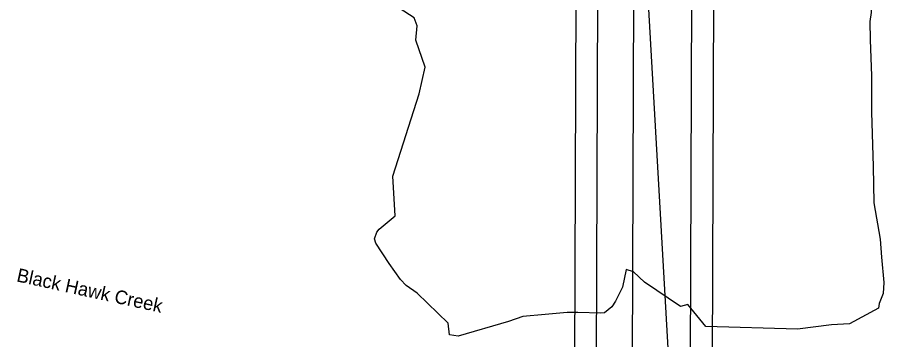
# Model space of a CAD drawing. Extents: x 15359458 to 15360238, y 8797399 to 8799222.
# Drawn here: x 15359587.4 to 15360065.7, y 8798185.5 to 8798363.3 of the extents above; entities that cross this region are included whole.
import ezdxf

# ---------------------------------------------------------------- set-up
doc = ezdxf.new("R2010")
doc.units = 0
for name, color, linetype in [('Alignment', 7, 'Continuous'), ('PhoTerrainTriangle', 7, 'Continuous'), ('PhoTerrainVoid', 7, 'Continuous'), ('TL_Barrier', 7, 'Continuous')]:
    doc.layers.add(name, color=color, linetype=linetype)

msp = doc.modelspace()

# ---------------------------------------------------------------- linework, layer by layer
at = {"layer": 'Alignment'}
for p, q in [((15359898.87, 8799211.58), (15359893.01, 8797661.59)), ((15359910.87, 8799211.53), (15359905.01, 8797661.54)), ((15359962.87, 8799211.33), (15359957.01, 8797661.35)), ((15359974.87, 8799211.29), (15359969.01, 8797661.3))]:
    msp.add_line(p, q, dxfattribs=at)
at = {"layer": 'PhoTerrainTriangle'}
for p, q in [((15359925.97, 8797914.04), (15359928.19, 8798502.04)), ((15359928.19, 8798502.04), (15359961.97, 8797913.9))]:
    msp.add_line(p, q, dxfattribs=at)
at = {"layer": 'TL_Barrier'}
for points in [[(15360042.66, 8798706.03), (15360043.62, 8798686.03), (15360044.9, 8798666.02), (15360045.39, 8798646.02), (15360046.67, 8798626.01), (15360047.54, 8798606.01), (15360048.03, 8798586.01), (15360048.57, 8798566.01), (15360049.85, 8798546), (15360050.34, 8798526), (15360052.2, 8798496.72), (15360052.96, 8798485.99), (15360054.26, 8798465.98), (15360053.83, 8798445.99), (15360054.98, 8798425.98), (15360056.9, 8798411.81), (15360056.96, 8798404.31), (15360058.16, 8798385.97), (15360058.9, 8798365.97), (15360058.02, 8798360.97), (15360058.36, 8798350.97), (15360058.97, 8798330.97), (15360059.03, 8798310.96), (15360059.86, 8798280.96)], [(15359795.94, 8798253.89), (15359794.63, 8798275.61), (15359809.24, 8798321.07), (15359812.56, 8798335.89), (15359807.38, 8798350.75), (15359808.18, 8798358.72), (15359806.42, 8798363.13), (15359798.28, 8798368.38), (15359791.96, 8798374.74), (15359789.53, 8798377.84), (15359787.48, 8798380.97), (15359785.6, 8798384.6), (15359784.15, 8798388.21), (15359783.05, 8798391.94), (15359782.33, 8798395.58), (15359781.96, 8798399.62)], [(15360059.86, 8798280.96), (15360060.31, 8798260.96), (15360063.77, 8798240.95), (15360064.46, 8798230.94), (15360065.73, 8798217.06), (15360065.4, 8798210.94), (15360063.18, 8798205.44), (15360062.87, 8798202.95), (15360046.95, 8798194.3), (15360036.95, 8798193.75), (15360018.07, 8798191.2), (15359967.55, 8798192.68), (15359957.65, 8798204.91), (15359953.56, 8798203.81), (15359933.61, 8798217.16), (15359927.63, 8798222.91), (15359923.63, 8798224.13), (15359921.6, 8798214.36), (15359917.57, 8798206.69), (15359915.56, 8798203.54), (15359911.54, 8798200.35), (15359909.54, 8798200.02), (15359896.82, 8798200.44), (15359890.92, 8798200.44), (15359878.85, 8798199.33), (15359866.4, 8798198.18), (15359858.64, 8798195.49), (15359830.85, 8798187.46), (15359826.05, 8798188.13), (15359825.28, 8798194.54), (15359808.06, 8798211.07), (15359802.06, 8798215.41), (15359798.98, 8798218.68), (15359792.6, 8798227.42), (15359785.29, 8798238.64), (15359784.57, 8798241.03), (15359785.86, 8798244.82), (15359787.12, 8798246.49), (15359795.94, 8798253.89)]]:
    msp.add_lwpolyline(points, dxfattribs=at)

# ---------------------------------------------------------------- texts
at = {"layer": 'PhoTerrainVoid'}
msp.add_text('Black Hawk Creek', height=7.5, rotation=347.7295, dxfattribs=at).set_placement((15359586.57, 8798217.69))

doc.saveas('drawing.dxf')
